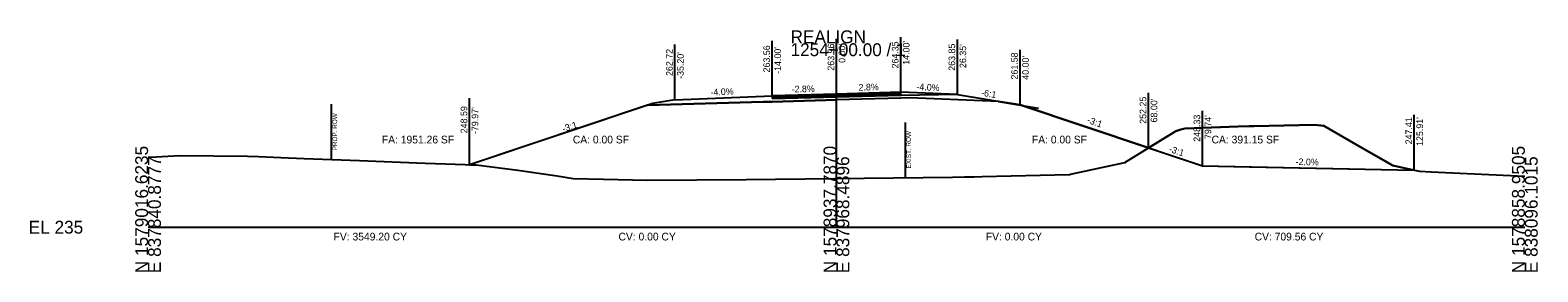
# Model space of a CAD drawing. Extents: x -26 to 6303, y -16 to 9563.
# Drawn here: x 2974.3 to 3302.8, y 5990.3 to 6042.8 of the extents above; entities that cross this region are included whole.
import ezdxf

# ---------------------------------------------------------------- set-up
doc = ezdxf.new("R2010")
doc.units = 0
for name, color, linetype in [('ASPHALT_19MM1', 7, 'Continuous'), ('ASPHALT_9_5MM1', 7, 'Continuous'), ('CONST_LV3', 7, 'Continuous'), ('CONST_PROF_LV1', 7, 'Continuous'), ('Draft_XS_Grid', 7, 'Continuous'), ('DTM_TEMP_DROP', 7, 'Continuous'), ('DTM_X_FLOW_ARROWS', 7, 'Continuous'), ('DTM_X_GROUND', 7, 'Continuous'), ('TRANS_BRIDGE', 7, 'Continuous'), ('XS_CELL', 7, 'Continuous'), ('XS_M_SHAPES_EARTHWORK', 7, 'Continuous'), ('XS_P_GROUND', 7, 'Continuous'), ('XS_P_NULL_POINT', 7, 'Continuous'), ('XS_P_ROW', 7, 'Continuous'), ('XS_P_SHOULDER', 7, 'Continuous'), ('XS_P_SUBGRADE_GRANULAR', 7, 'Continuous'), ('XS_P_TX_CLEARZONE', 7, 'Continuous'), ('XS_P_TX_FS_BS', 7, 'Continuous'), ('XS_PLAN_CLEAR_ZONE', 7, 'Continuous'), ('XS_SHEET_EW_TX_AREA', 7, 'Continuous'), ('XS_SHEET_EW_TX_VOLUME', 7, 'Continuous'), ('XS_X_ROW', 7, 'Continuous')]:
    doc.layers.add(name, color=color, linetype=linetype)

msp = doc.modelspace()

# ---------------------------------------------------------------- linework, layer by layer
at = {"layer": 'ASPHALT_19MM1'}
msp.add_lwpolyline([(3136, 6027.96), (3136, 6027.96), (3136, 6027.96), (3150, 6028.35), (3150, 6028.35), (3164, 6028.74), (3164, 6028.74), (3164, 6029.01), (3150, 6028.62), (3150, 6028.62), (3136, 6028.23), (3136, 6028.23), (3136, 6027.96)], dxfattribs=at)
at = {"layer": 'ASPHALT_9_5MM1'}
msp.add_lwpolyline([(3136, 6028.44), (3136, 6028.44), (3136, 6028.44), (3150, 6028.83), (3150, 6028.83), (3164, 6029.22), (3164, 6029.22), (3164, 6029.35), (3150, 6028.96), (3150, 6028.96), (3136, 6028.56), (3136, 6028.56), (3136, 6028.44)], dxfattribs=at)
at = {"layer": 'CONST_LV3'}
for points in [[(3150, 6028.96), (3164, 6028.68)], [(3176.35, 6028.85), (3164, 6028.68), (3164, 6028.68)], [(3185.31, 6027.36), (3194, 6025.91)]]:
    msp.add_lwpolyline(points, dxfattribs=at)
at = {"layer": 'DTM_X_GROUND'}
msp.add_lwpolyline([(3000, 6015.26), (3001.77, 6015.34), (3006.89, 6015.56), (3021.65, 6015.48), (3024.1, 6015.37), (3028.91, 6015.15), (3034.03, 6014.96), (3046.1, 6014.5), (3060.38, 6013.9), (3071.31, 6013.55), (3071.45, 6013.54), (3071.5, 6013.53), (3080.59, 6012.43), (3086.12, 6011.59), (3089.17, 6011.18), (3092.66, 6010.59), (3099.26, 6010.44), (3108.77, 6010.22), (3130.35, 6010.41), (3175.26, 6010.88), (3177.94, 6010.93), (3179.99, 6010.99), (3181.77, 6011.03), (3200.71, 6011.49), (3200.88, 6011.49), (3201.01, 6011.52), (3212.82, 6014.04), (3216.24, 6016.17), (3223.94, 6020.92), (3225.06, 6021.26), (3225.89, 6021.5), (3237.55, 6021.89), (3239.94, 6021.98), (3240.93, 6021.99), (3254.2, 6022.24), (3255.57, 6022.12), (3256.22, 6022.06), (3264.51, 6017.28), (3271.27, 6013.39), (3274.11, 6012.79), (3277.06, 6012.17), (3279.62, 6012.05), (3300, 6011.11)], dxfattribs=at)
at = {"layer": 'XS_CELL'}
for p, q in [((3150, 6000), (3150, 6040)), ((3000, 6000), (3150, 6000)), ((3150, 6000), (3300, 6000))]:
    msp.add_line(p, q, dxfattribs=at)
at = {"layer": 'XS_M_SHAPES_EARTHWORK'}
msp.add_lwpolyline([(3070.03, 6013.59), (3071.31, 6013.55), (3071.45, 6013.54), (3071.5, 6013.53), (3080.59, 6012.43), (3086.12, 6011.59), (3089.17, 6011.18), (3092.66, 6010.59), (3099.26, 6010.44), (3108.77, 6010.22), (3130.35, 6010.41), (3175.26, 6010.88), (3177.94, 6010.93), (3179.99, 6010.99), (3181.77, 6011.03), (3200.71, 6011.49), (3200.88, 6011.49), (3201.01, 6011.52), (3212.82, 6014.04), (3216.24, 6016.17), (3218, 6017.25), (3190, 6026.58), (3185.31, 6027.36), (3166, 6028.13), (3164, 6028.08), (3150, 6027.68), (3136, 6027.29), (3134, 6027.24), (3108.85, 6026.53)], close=True, dxfattribs=at)
at = {"layer": 'XS_P_GROUND'}
for points in [[(3176.35, 6028.85), (3190, 6026.58), (3218, 6017.25)], [(3176.35, 6028.85), (3190, 6026.58), (3229.74, 6013.33)], [(3114.8, 6027.72), (3110, 6026.92), (3070.03, 6013.59)], [(3229.74, 6013.33), (3240.03, 6013.13)], [(3240.03, 6013.13), (3275.91, 6012.41)]]:
    msp.add_lwpolyline(points, dxfattribs=at)
at = {"layer": 'XS_P_ROW'}
msp.add_line((3040, 6014.73), (3040, 6026.73), dxfattribs=at)
at = {"layer": 'XS_P_SHOULDER'}
for points in [[(3176.35, 6028.85), (3164, 6029.35), (3164, 6029.35)], [(3114.8, 6027.72), (3136, 6028.56), (3136, 6028.56)]]:
    msp.add_lwpolyline(points, dxfattribs=at)
at = {"layer": 'XS_P_SUBGRADE_GRANULAR'}
for points in [[(3108.85, 6026.53), (3134, 6027.24), (3134, 6027.24), (3134, 6027.24), (3136, 6027.29)], [(3136, 6027.29), (3136, 6027.29), (3150, 6027.68)], [(3164, 6028.08), (3150, 6027.68), (3150, 6027.68)], [(3185.31, 6027.36), (3166, 6028.13), (3166, 6028.13), (3164, 6028.08), (3164, 6028.08)]]:
    msp.add_lwpolyline(points, dxfattribs=at)
at = {"layer": 'XS_P_TX_CLEARZONE'}
for p, q in [((3114.8, 6027.72), (3114.8, 6039.72)), ((3136, 6028.56), (3136, 6040.56)), ((3150, 6028.96), (3150, 6040.96)), ((3164, 6029.35), (3164, 6041.35)), ((3176.35, 6028.85), (3176.35, 6040.85)), ((3176.35, 6028.85), (3176.35, 6040.85)), ((3190, 6026.58), (3190, 6038.58)), ((3218, 6017.25), (3218, 6029.25)), ((3070.03, 6013.59), (3070.03, 6028.03)), ((3229.74, 6013.33), (3229.74, 6025.33)), ((3275.91, 6012.41), (3275.91, 6024.41))]:
    msp.add_line(p, q, dxfattribs=at)
at = {"layer": 'XS_P_TX_FS_BS'}
for p, q in [((3217.99, 6017.25), (3229.74, 6013.33)), ((3229.74, 6013.33), (3275.91, 6012.41))]:
    msp.add_line(p, q, dxfattribs=at)
msp.add_lwpolyline([(3275.91, 6012.41), (3274.11, 6012.79), (3271.27, 6013.39), (3264.51, 6017.28), (3256.22, 6022.06), (3255.57, 6022.12), (3254.2, 6022.24), (3240.93, 6021.99), (3239.94, 6021.98), (3237.55, 6021.89), (3225.89, 6021.5), (3225.06, 6021.26), (3223.94, 6020.92), (3217.99, 6017.25)], dxfattribs=at)
at = {"layer": 'XS_PLAN_CLEAR_ZONE'}
msp.add_lwpolyline([(3136, 6028.23), (3136, 6028.23), (3136, 6028.23), (3150, 6028.62), (3150, 6028.62), (3164, 6029.01), (3164, 6029.01), (3164, 6029.22), (3150, 6028.83), (3150, 6028.83), (3136, 6028.44), (3136, 6028.44), (3136, 6028.23)], dxfattribs=at)
at = {"layer": 'XS_X_ROW'}
msp.add_line((3165.03, 6010.77), (3165.03, 6022.77), dxfattribs=at)

# ---------------------------------------------------------------- texts
at = {"layer": 'CONST_PROF_LV1'}
for p in [(3217.92, 6017.13), (3069.95, 6013.47)]:
    msp.add_text('X', height=0.24, dxfattribs=at).set_placement(p)
at = {"layer": 'Draft_XS_Grid'}
msp.add_text('-', height=0.0001, dxfattribs=at).set_placement((3000, 6000))
at = {"layer": 'DTM_TEMP_DROP'}
for p in [(3135.92, 6028.44), (3149.92, 6028.84), (3163.92, 6029.23)]:
    msp.add_text('X', height=0.24, dxfattribs=at).set_placement(p)
at = {"layer": 'DTM_X_FLOW_ARROWS'}
msp.add_text('X', height=0.24, dxfattribs=at).set_placement((3275.83, 6012.29))
at = {"layer": 'TRANS_BRIDGE'}
for p in [(3217.92, 6017.13), (3069.95, 6013.47)]:
    msp.add_text('X', height=0.24, dxfattribs=at).set_placement(p)
at = {"layer": 'XS_CELL'}
for s, p in [('REALIGN', (3140, 6040)), ('1254+00.00 / 1', (3140, 6037.2)), ('EL 235', (2974, 5998.6))]:
    msp.add_text(s, height=2.8, dxfattribs=at).set_placement(p)
for s, p in [('N 1579016.6235', (3000, 5990)), ('N 1578937.7870', (3150, 5990)), ('N 1578858.9505', (3300, 5990)), ('E 837840.8777', (3002.8, 5990)), ('E 837968.4896', (3152.8, 5990)), ('E 838096.1015', (3302.8, 5990))]:
    msp.add_text(s, height=2.8, rotation=90, dxfattribs=at).set_placement(p)
at = {"layer": 'XS_P_GROUND'}
msp.add_text('X', height=0.24, dxfattribs=at).set_placement((3193.92, 6025.79))
at = {"layer": 'XS_P_NULL_POINT'}
for p in [(3176.27, 6028.73), (3189.92, 6026.46)]:
    msp.add_text('X', height=0.24, dxfattribs=at).set_placement(p)
at = {"layer": 'XS_P_ROW'}
msp.add_text('PROP. ROW', height=1, rotation=90, dxfattribs=at).set_placement((3041.2, 6016.73))
at = {"layer": 'XS_P_SHOULDER'}
for p in [(3176.27, 6028.73), (3114.72, 6027.6)]:
    msp.add_text('X', height=0.24, dxfattribs=at).set_placement(p)
at = {"layer": 'XS_P_SUBGRADE_GRANULAR'}
msp.add_text('X', height=0.24, dxfattribs=at).set_placement((3229.66, 6013.21))
at = {"layer": 'XS_P_TX_CLEARZONE'}
for s, p in [('262.72', (3114.32, 6032.89)), ('263.56', (3135.52, 6033.66)), ("-14.00'", (3137.92, 6033.36)), ('263.96', (3149.52, 6034.05)), ("0.00'", (3151.92, 6035.74)), ('264.35', (3163.52, 6034.52)), ("14.00'", (3165.92, 6035.32)), ('263.85', (3175.87, 6034.03)), ("26.35'", (3178.27, 6034.62)), ("-35.20'", (3116.72, 6032.26)), ('261.58', (3189.52, 6032.12)), ("40.00'", (3191.92, 6032.07)), ('248.59', (3069.55, 6020.43)), ("-79.97'", (3071.95, 6020.26)), ('252.25', (3217.52, 6022.49)), ("68.00'", (3219.92, 6022.79)), ('248.33', (3229.26, 6018.58)), ("79.74'", (3231.66, 6019.17)), ('247.41', (3275.43, 6018.02)), ("125.91'", (3277.83, 6017.68))]:
    msp.add_text(s, height=1.44, rotation=90, dxfattribs=at).set_placement(p)
at = {"layer": 'XS_P_TX_FS_BS'}
for s, rotation, p in [('-4.0%', 2.2906, (3122.58, 6028.63)), ('-2.8%', 1.6039, (3140.25, 6029.28)), ('2.8%', 1.6039, (3154.84, 6029.69)), ('-4.0%', 357.7094, (3167.41, 6029.81)), ('-6:1', 350.5377, (3181.45, 6028.61)), ('-3:1', 17.5075, (3090.5, 6020.68)), ('-3:1', 340.1467, (3204.5, 6022.76)), ('-3:1', 341.563, (3222.33, 6016.43)), ('-2.0%', 358.8542, (3250.04, 6013.53))]:
    msp.add_text(s, height=1.44, rotation=rotation, dxfattribs=at).set_placement(p)
at = {"layer": 'XS_SHEET_EW_TX_AREA'}
for s, p in [('FA: 1951.26 SF', (3050.95, 6018.22)), ('CA: 0.00 SF', (3092.56, 6018.22)), ('FA: 0.00 SF', (3192.6, 6018.22)), ('CA: 391.15 SF', (3231.74, 6018.22))]:
    msp.add_text(s, height=1.68, dxfattribs=at).set_placement(p)
at = {"layer": 'XS_SHEET_EW_TX_VOLUME'}
for s, p in [('FV: 3549.20 CY', (3040.43, 5997.12)), ('CV: 0.00 CY', (3102.51, 5997.12)), ('FV: 0.00 CY', (3182.55, 5997.12)), ('CV: 709.56 CY', (3241.13, 5997.12))]:
    msp.add_text(s, height=1.68, dxfattribs=at).set_placement(p)
at = {"layer": 'XS_X_ROW'}
msp.add_text('EXIST. ROW', height=1, rotation=90, dxfattribs=at).set_placement((3166.23, 6012.77))

doc.saveas('drawing.dxf')
